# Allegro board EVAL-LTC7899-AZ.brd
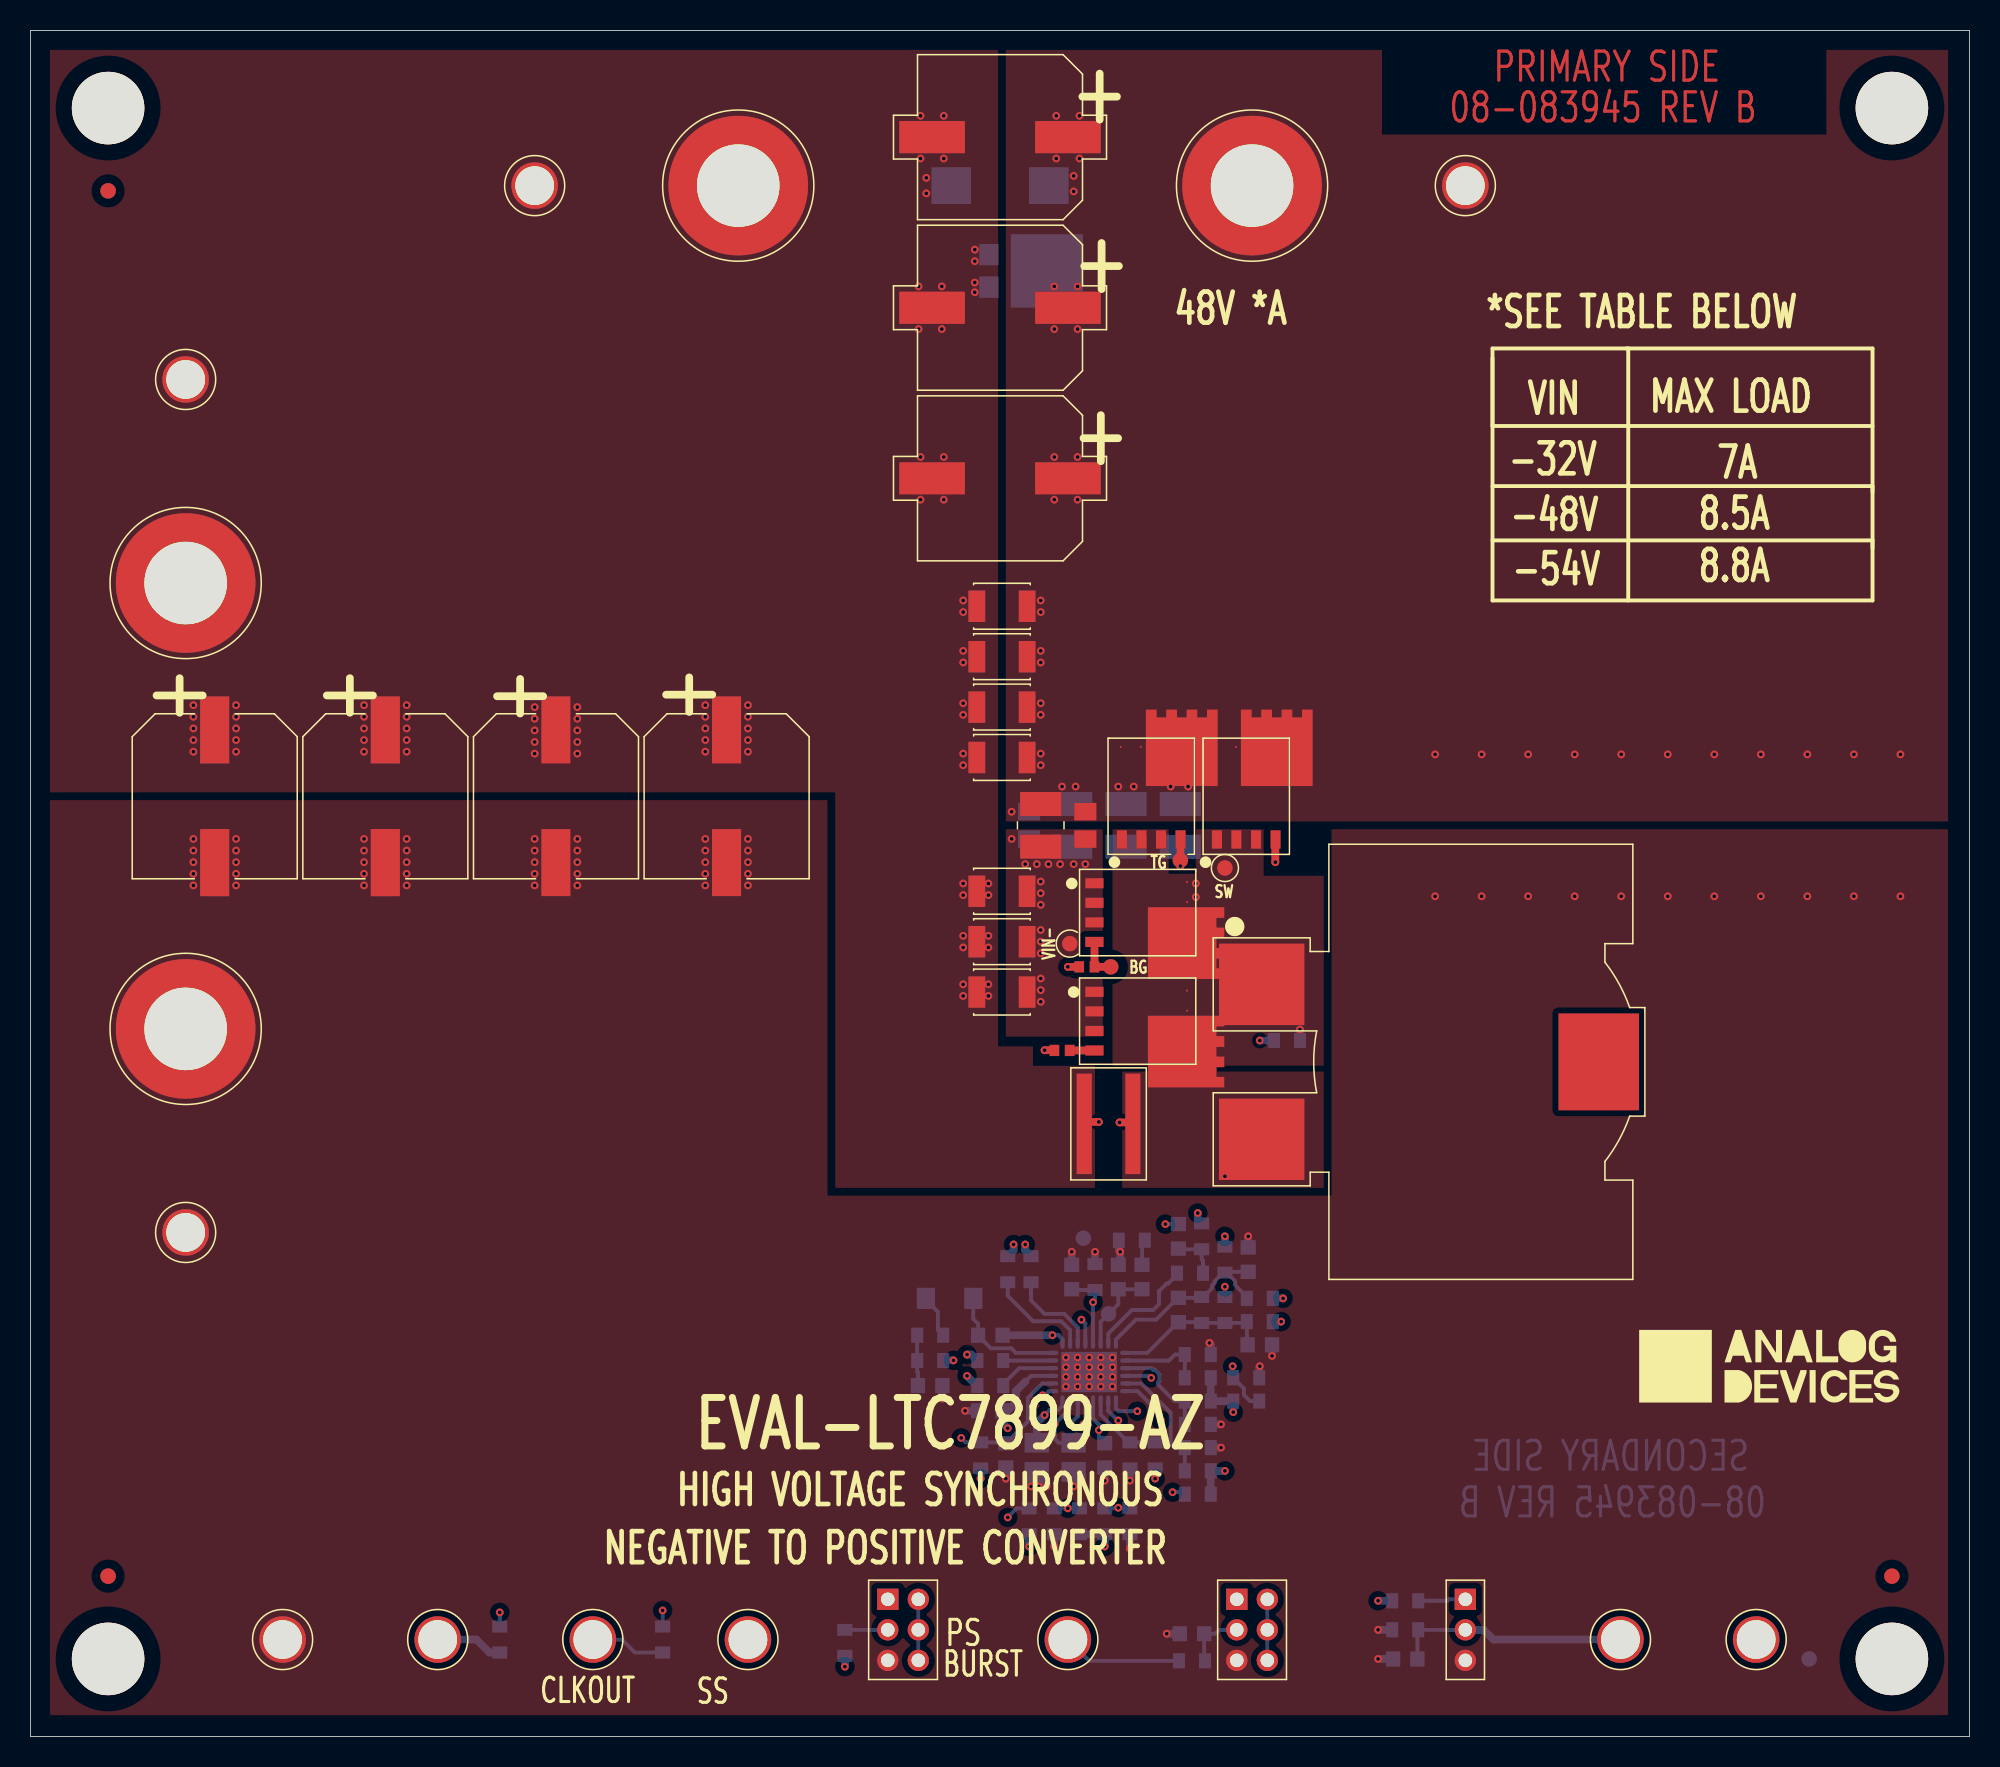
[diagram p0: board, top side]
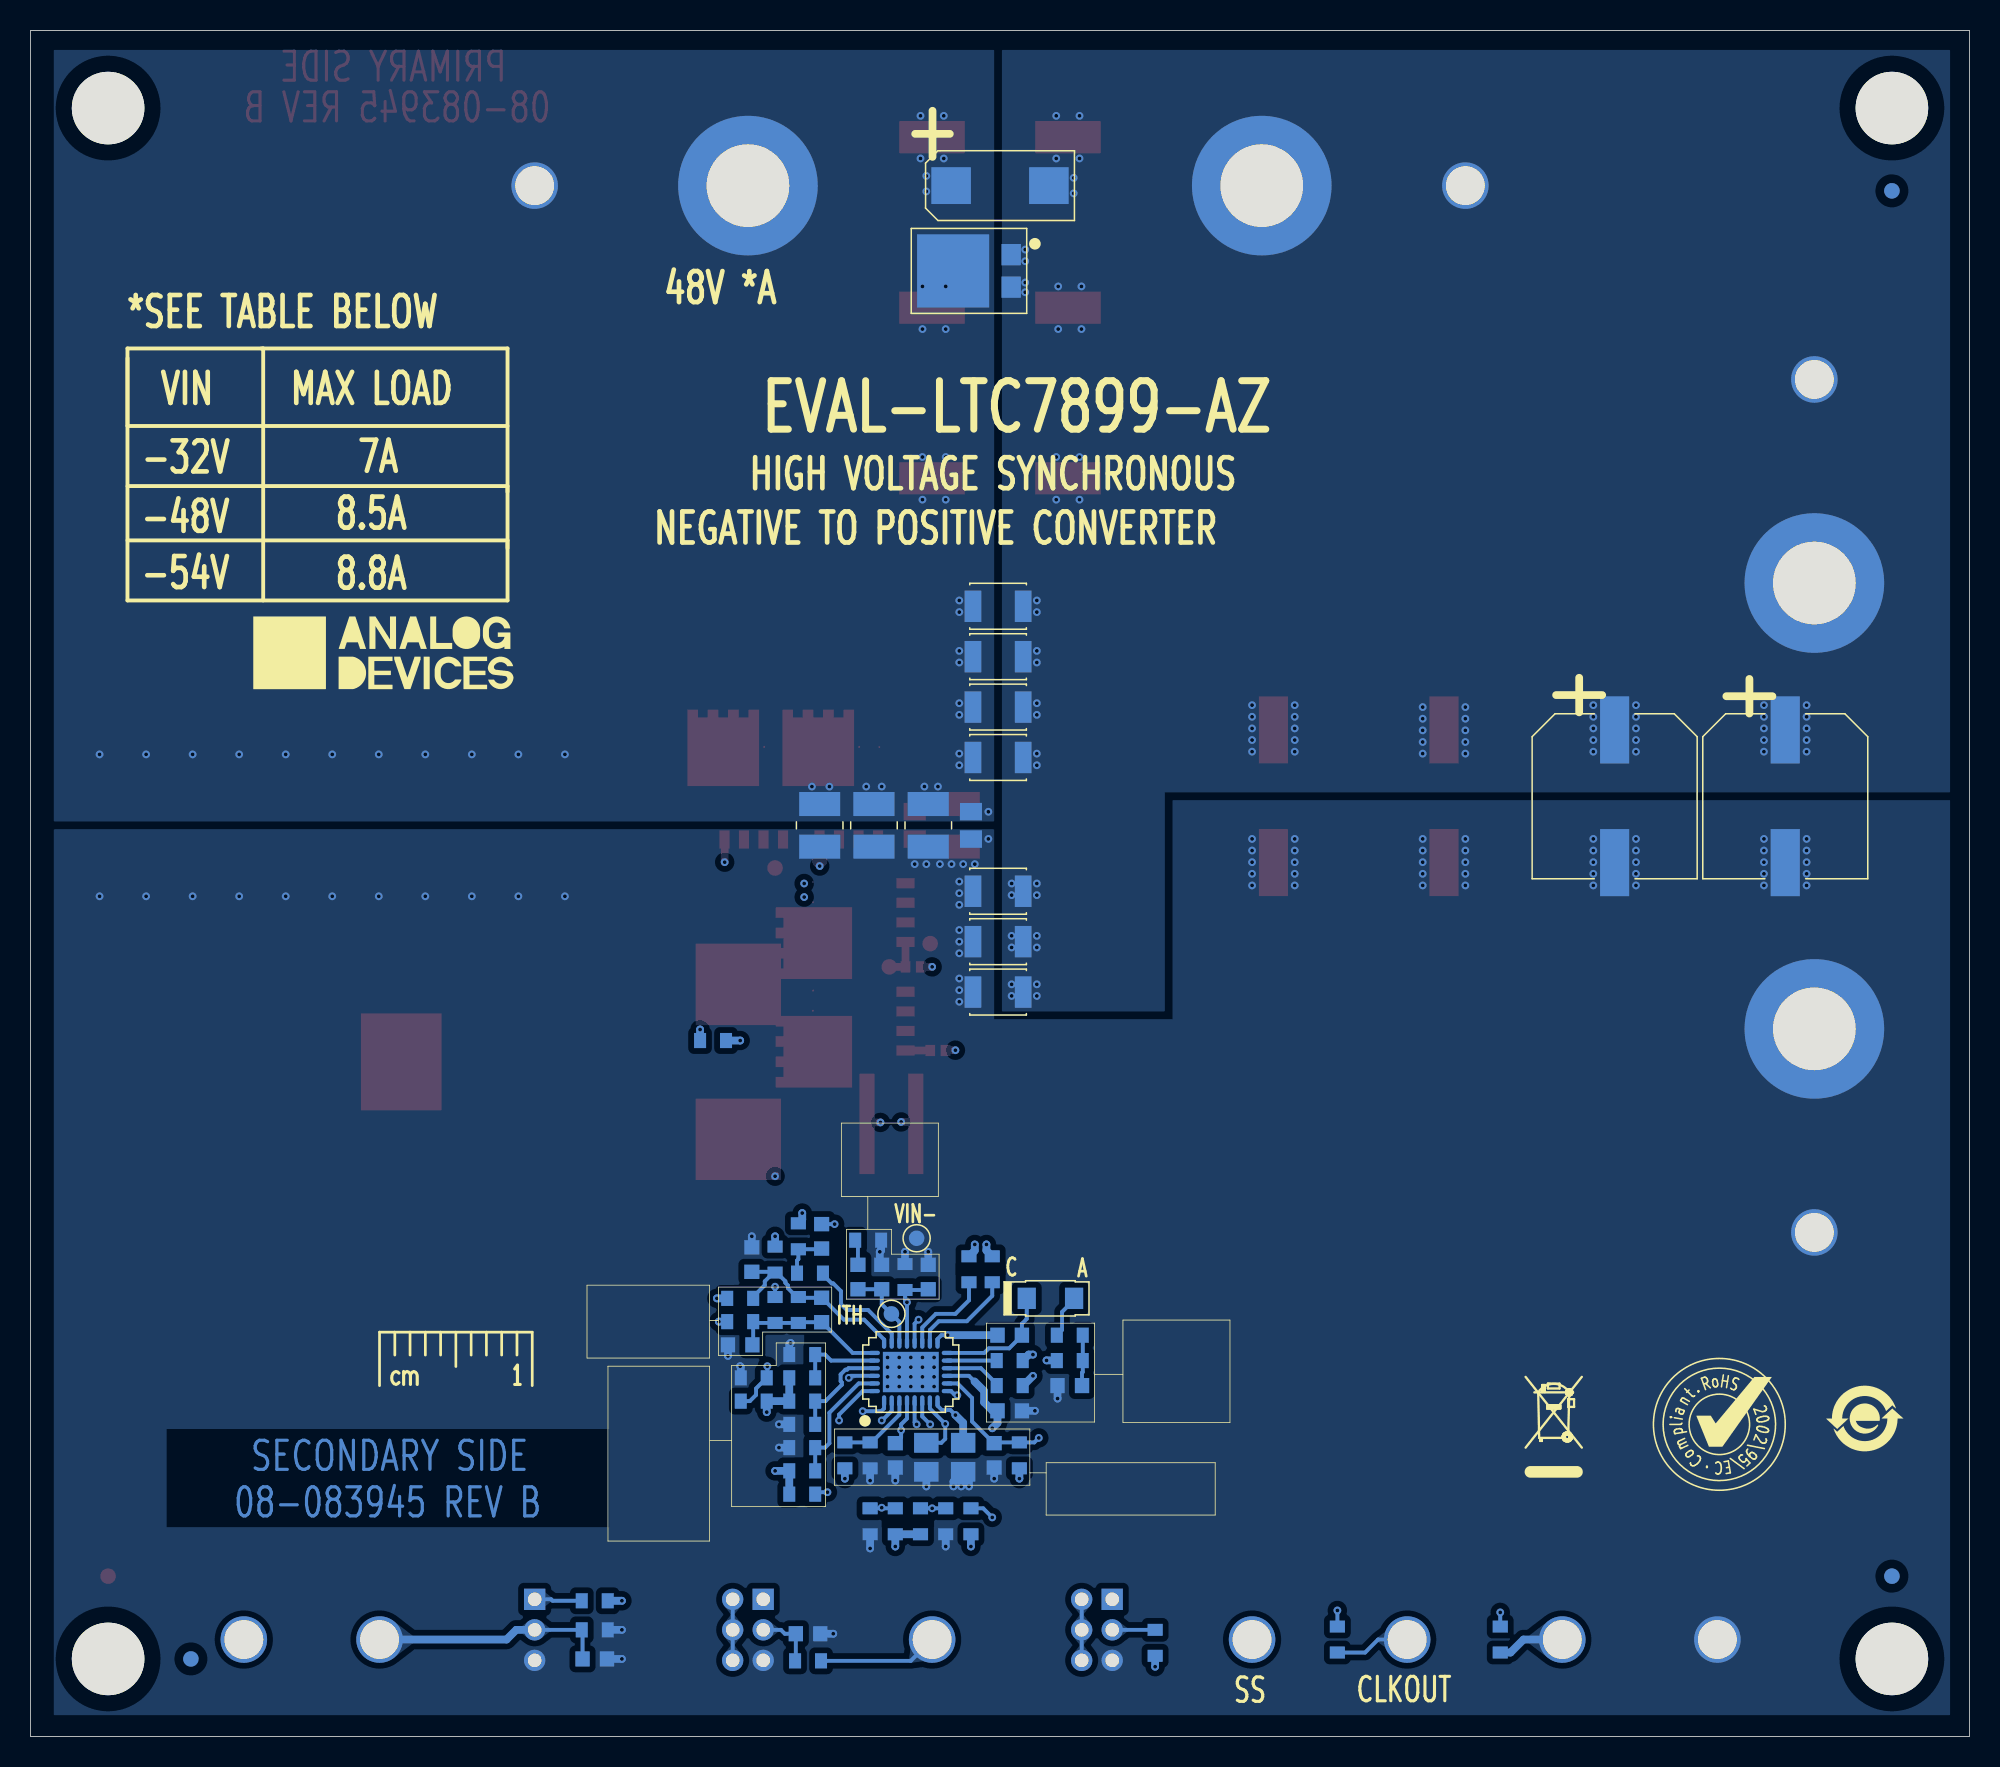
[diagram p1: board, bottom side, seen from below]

Outline 127 x 111.76 mm; copper layers: TOP, LAYER_2, LAYER_3, LAYER_4, LAYER_5, BOTTOM. Coordinates in mm from the lower left corner of the outline.
Outline path: 0,111.76 0,0 127,0 127,111.76 0,111.76

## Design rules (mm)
constraint set DEFAULT: min track width 0.254
net group _N80: nets _N80 _N81
net group _N135: nets _N40 _N135
net group _N17: nets _N17 _N18 _N19
net group _N44: nets _N42 _N43 _N44
net group _N59: nets _N52 _N53 _N54 _N59 _N60
net group _N63: nets _N45 _N46 _N63 _N64

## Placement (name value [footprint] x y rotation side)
C1  TBD0603  [C0603]  79.76 31.24 90 bottom
C2  TBD0603  [C0603]  80.52 25.65 0 bottom
C3  0.1UF  [C0603]  62.86 26.29 180 bottom
C4  56UF  [CPLSMSQ406H500]  23.24 61.59 270 bottom
C5  56UF  [CPLSMSQ406H500]  12.07 61.59 270 bottom
C6  0.22uF  [C1210-2]  66.17 59.69 270 top
C7  1000pF  [C0603]  75.18 27.94 270 bottom
C8  TBD0603  [C0603]  68.2 30.1 270 bottom
C9  0.1UF  [C0805H55]  69.09 59.69 270 top
C10  470pF  [C0603]  71.25 30.1 90 bottom
C11  0.22uF  [C1210-2]  68.2 59.69 270 bottom
C12  0.22uF  [C1210-2]  71.75 59.69 270 bottom
C13  0.22uF  [C1210-2]  75.31 59.69 270 bottom
C14  0.015UF  [C0603]  72.8 30.1 90 bottom
C15  0.1uF  [C0805H60]  68.33 18.29 270 bottom
C16  TBD0603  [C0603]  76.07 6.73 180 bottom
C17  0.1UF  [C0603]  70.36 18.41 270 bottom
C18  0.1UF  [C0805H55]  65.41 59.69 270 bottom
C19  0.1UF  [C0603]  58.93 22.99 0 bottom
C20  10UF  [C1210H106]  63.63 48.77 0 top
C21  10UF  [C1210H106]  63.63 52.07 0 top
C22  10UF  [C1210H106]  63.63 55.37 0 top
C23  TBD0603  [C0603]  63.88 18.41 270 bottom
C24  100PF  [C0603]  90.04 5.08 180 bottom
C26  0.1UF  [C0603]  62.86 21.34 180 bottom
C27  4.7uF  [C0805H53]  65.91 18.29 270 bottom
C28  TBD0603  [C0603]  75.18 32.77 90 bottom
C30  56UF  [CPLSMSQ406H500]  12.07 61.59 270 top
C31  56UF  [CPLSMSQ406H500]  23.24 61.59 270 top
C32  56UF  [CPLSMSQ406H500]  34.42 61.59 270 top
C33  56UF  [CPLSMSQ406H500]  45.59 61.59 270 top
C34  10UF  [C1210H106]  63.63 55.37 0 bottom
C35  10UF  [C1210H106]  63.63 52.07 0 bottom
C36  10UF  [C1210H106]  63.63 48.77 0 bottom
COUT1  68UF  [CPLSMSQ406H413]  63.5 104.77 180 top
COUT2  68UF  [CPLSMSQ406H413]  63.5 93.6 180 top
COUT3  68UF  [CPLSMSQ406H413]  63.5 82.42 180 top
COUT4  TBD7343  [C7343H162]  63.5 101.6 180 bottom
COUT5  10UF  [C1210H106]  63.63 74.04 180 top
COUT6  10UF  [C1210H106]  63.63 70.74 180 top
COUT7  10UF  [C1210H106]  63.63 67.44 180 top
COUT8  10UF  [C1210H106]  63.63 64.14 180 top
COUT9  10UF  [C1210H106]  63.63 74.04 180 bottom
COUT10  10UF  [C1210H106]  63.63 70.74 180 bottom
COUT11  10UF  [C1210H106]  63.63 67.44 180 bottom
COUT12  10UF  [C1210H106]  63.63 64.14 180 bottom
D1  PNE20010ERX  [SOD123W]  60.2 28.7 180 bottom
D2  SS8P3LHM3_A/H  [TO-277A]  65.53 96.01 0 bottom
E2  2501-2-00-80-00-00-07-0  [CNMILLMAX2501]  113.03 6.35 0 top
E6  2501-2-00-80-00-00-07-0  [CNMILLMAX2501]  10.16 88.9 0 top
E8  2501-2-00-80-00-00-07-0  [CNMILLMAX2501]  10.16 33.02 0 top
E10  2501-2-00-80-00-00-07-0  [CNMILLMAX2501]  67.95 6.35 0 top
E11  2501-2-00-80-00-00-07-0  [CNMILLMAX2501]  46.99 6.35 0 top
E12  2501-2-00-80-00-00-07-0  [CNMILLMAX2501]  26.67 6.35 0 top
E16  2501-2-00-80-00-00-07-0  [CNMILLMAX2501]  104.14 6.35 0 top
E18  2501-2-00-80-00-00-07-0  [CNMILLMAX2501]  33.02 101.6 0 top
E19  2501-2-00-80-00-00-07-0  [CNMILLMAX2501]  93.98 101.6 0 top
E20  2501-2-00-80-00-00-07-0  [CNMILLMAX2501]  16.51 6.35 0 top
E21  2501-2-00-80-00-00-07-0  [CNMILLMAX2501]  36.83 6.35 0 top
J1  575-4  [CNBANANAD312LD203]  80.01 101.6 0 top
J2  575-4  [CNBANANAD312LD203]  46.35 101.6 0 top
J3  575-4  [CNBANANAD312LD203]  10.16 75.56 0 top
J4  575-4  [CNBANANAD312LD203]  10.16 46.35 0 top
JP1  62000621121  [CNTHMHDR2X3L236W157H248]  56.15 8.98 270 top
JP2  62000311121  [CNTHMHDR1X3L236W79H244]  93.98 8.98 270 top
JP3  62000621121  [CNTHMHDR2X3L236W157H248]  79.01 8.98 270 top
L1  15UH  [LSML1102W764H728]  92.2 44.2 270 top
NOREF  -  []  -222.25 -135.89 0 top
NOREF#2  -  []  200.56 73.18 0 top
NOREF#3  -  []  0 111.76 0 top
NOREF#4  -  []  0 0 0 top
NOREF#5  -  []  113.92 24.26 0 top
NOREF#6  -  []  163.07 61.21 0 top
NOREF#7  -  [unnamed#2]  121.92 5.08 180 top
NOREF#8  -  []  5.08 5.08 0 top
NOREF#9  -  []  5.08 5.08 0 top
NOREF#10  -  []  152.53 -3.68 0 top
NOREF#11  -  []  -76.2 -66.04 0 top
NOREF#12  -  [unnamed#2]  5.08 106.68 180 top
NOREF#13  -  []  244.35 296.16 0 top
NOREF#14  -  []  0 0 0 top
NOREF#15  -  []  64.14 0.63 270 top
NOREF#16  -  []  163.07 54.23 0 top
NOREF#17  -  [unnamed#2]  121.92 106.68 180 top
NOREF#18  -  []  250.19 261.75 0 top
NOREF#19  -  []  0 111.76 0 top
NOREF#20  -  [unnamed#2]  5.08 10.5 0 top
NOREF#21  -  []  -76.2 -66.04 0 top
NOREF#22  -  []  152.53 -13.59 0 top
NOREF#23  -  []  127 111.76 180 top
NOREF#24  -  []  127 0 0 top
NOREF#25  -  []  127 0 90 top
NOREF#26  -  [unnamed#2]  5.08 5.08 180 top
NOREF#27  -  []  82.17 105.16 0 top
NOREF#28  -  []  59.69 117.47 0 top
NOREF#29  -  []  95 102.87 0 top
NOREF#30  -  []  0 0 0 top
NOREF#31  -  []  178.56 36.45 0 top
NOREF#32  -  []  340.83 78.68 0 top
NOREF#33  -  [unnamed#2]  5.08 101.26 180 top
NOREF#34  -  []  308.39 131.71 0 top
NOREF#35  -  []  -222.25 -135.89 0 top
NOREF#36  -  [unnamed#2]  121.92 10.5 0 top
NOREF#37  -  []  -76.2 -66.04 0 top
NOREF#38  -  []  127 0 90 top
NOREF#39  -  []  0 111.76 270 top
NOREF#40  -  []  124.08 108.46 0 top
NOREF#41  -  []  104.14 22.99 180 bottom
NOREF#42  -  [unnamed#2]  5.08 101.26 0 bottom
NOREF#43  -  []  103.86 70.99 180 bottom
NOREF#44  -  []  27.43 17.02 180 bottom
NOREF#45  -  []  16.38 20.45 180 bottom
NOREF#46  -  []  6.86 20.83 180 bottom
NOREF#47  -  [unnamed#2]  5.08 10.5 180 bottom
NOREF#48  -  [unnamed#2]  116.5 5.08 270 bottom
Q1  ISC078N12NM6ATMA1  [SON8]  73.41 61.59 0 top
Q2  ISC110N12NM6ATMA1  [SON8]  79.63 61.59 0 top
Q3  ISC078N12NM6ATMA1  [SON8]  72.52 53.98 270 top
Q4  ISC078N12NM6ATMA1  [SON8]  72.52 46.86 270 top
R1  0  [R0402]  69.19 50.42 0 top
R2  0  [R0402]  67.56 44.94 0 top
R3  0  [R0603]  72.01 14.1 90 bottom
R4  TBD0603  [R0603]  70.36 14.1 90 bottom
R5  1MEG  [R0603]  76.45 15.88 180 bottom
R6  0  [R0603]  65.53 30.61 90 bottom
R7  0  [R0603]  41.4 6.35 90 bottom
R8  0  [R0603]  64.01 30.61 90 bottom
R9  316K  [R0603]  90.04 8.89 180 bottom
R10  0  [R0603]  68.71 14.1 90 bottom
R11  TBD0603  [R0603]  67.06 14.1 90 bottom
R12  13.3K  [R0603]  90.04 6.99 180 bottom
R13  5.11  [R0603]  62.86 22.99 180 bottom
R14  TBD0603  [R0603]  76.45 18.92 0 bottom
R15  0  [R0603]  62.86 24.63 180 bottom
R16  0  [R0603]  76.45 17.4 0 bottom
R17  402K  [R0603]  75.95 30.35 180 bottom
R18  0  [R0603]  76.71 32.77 270 bottom
R19  10K  [R0603]  69.72 30.1 270 bottom
R20  10K  [R0603]  72.14 32.51 180 bottom
R21  TBD0603  [R0603]  30.73 6.35 270 bottom
R22  0  [R0603]  79.63 21.97 180 bottom
R23  TBD0603  [R0603]  79.63 23.49 0 bottom
R24  0  [R0603]  76.45 23.49 0 bottom
R25  0  [R0603]  80.52 27.18 180 bottom
R26  21K  [R0603]  76.45 25.02 0 bottom
R27  0  [R0603]  76.45 21.97 0 bottom
R28  20K  [R0603]  76.45 20.45 0 bottom
R29  51.1  [R0603]  80.52 28.7 180 bottom
R30  TBD0603  [R0603]  78.23 27.94 270 bottom
R31  0  [R0603]  58.93 26.29 180 bottom
R32  0  [R0603]  58.93 24.63 0 bottom
R33  TBD0603  [R0603]  82.3 45.59 180 bottom
R34  TBD0603  [R0603]  76.71 27.94 270 bottom
R35  TBD0603  [R0603]  78.23 31.24 270 bottom
R36  0  [R0603]  62.23 18.41 270 bottom
R37  249K  [R0603]  72.01 18.41 90 bottom
R38  TBD0603  [R0603]  73.66 18.41 90 bottom
R39  1K  [R0603]  76.07 4.95 0 bottom
R40  100K  [R0603]  53.34 6.14 90 bottom
R41  0  [R0603]  65.41 14.1 270 bottom
RSNS1  0.002  [R1225H28]  70.61 40.13 180 top
TP1  TESTPAD  [TPSMC40]  78.23 56.9 0 top
TP2  TESTPAD  [TPSMC40]  75.31 57.4 0 top
TP3  TESTPAD  [TPSMC40]  70.75 50.42 0 top
TP4  TESTPAD  [TPSMC40]  68.07 51.94 0 top
TP5  TESTPAD  [TPSMC40]  68.96 32.64 180 bottom
TP6  TESTPAD  [TPSMC40]  70.61 27.69 180 bottom
U1  LTC7899RUFD#PBF  [QFN28_5X4_PAD3_65X2_65_05-08-1712]  69.34 23.88 180 bottom

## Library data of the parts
C1 C2 C8 C16 C23 C28 = CAP: User Part Number: UPN; alternate symbols: (C0603)
C3 C7 C14 C17 C19 C24 C26 = CAP: User Part Number: UPN; Tolerance: 10; alternate symbols: (C0603); tolerance: 10
C4 C5 C30-C33 = CAPP: Tolerance: 20; User Part Number: UPN; alternate symbols: (CPLSMSQ406H500); tolerance: 20
C6 C11-C13 = CAP: Tolerance: 10; User Part Number: UPN; alternate symbols: (C1210-2); tolerance: 10
C9 C18 = CAP: User Part Number: UPN; Tolerance: 10; alternate symbols: (C0805H55); tolerance: 10
C10 = CAP: User Part Number: UPN; Tolerance: 1; alternate symbols: (C0603); tolerance: 1
C15 = CAP: Tolerance: 10; User Part Number: UPN; alternate symbols: (C0805H60); tolerance: 10
C20-C22 C34-C36 COUT5-COUT12 = CAP: Tolerance: 10; User Part Number: UPN; alternate symbols: (C1210H106); tolerance: 10
C27 = CAP: Tolerance: 10; User Part Number: UPN; alternate symbols: (C0805H53); tolerance: 10
COUT1-COUT3 = CAPP: User Part Number: UPN; Tolerance: 20; alternate symbols: (CPLSMSQ406H413); tolerance: 20
COUT4 = CAPP: User Part Number: UPN; alternate symbols: (C7343H162)
D1 = DIO: User Part Number: UPN; Tolerance: N/A; alternate symbols: (SOD123W); tolerance: N/A
D2 = DIO3P_V7: User Part Number: UPN; Tolerance: N/A; alternate symbols: (TO-277A); tolerance: N/A
E2 E6 E8 E10-E12 E16 E18-E21 = CNTP1P: User Part Number: UPN; Tolerance: N/A; alternate symbols: (CNMILLMAX2501); tolerance: N/A
J1-J4 = CNTP1P: Tolerance: N/A; User Part Number: UPN; alternate symbols: (CNBANANAD312LD203); tolerance: N/A
JP1 JP3 = CN6P_JMPRSHRT: User Part Number: UPN; Tolerance: N/A; alternate symbols: (CNTHMHDR2X3L236W157H248); tolerance: N/A
JP2 = CN3P: User Part Number: UPN; Tolerance: N/A; alternate symbols: (CNTHMHDR1X3L236W79H244); tolerance: N/A
L1 = IND: User Part Number: UPN; Tolerance: 15; alternate symbols: (LSML1102W764H728); tolerance: 15
Q1-Q4 = TRANNMOSFET8P: Tolerance: N/A; User Part Number: UPN; alternate symbols: (SON8); tolerance: N/A
R1 R2 = RES: User Part Number: UPN; Tolerance: JUMPER; alternate symbols: (R0402); tolerance: JUMPER
R3 R6-R8 R10 R15 R16 R18 R22 R24 R25 R27 R31 R32 R36 R41 = RES: User Part Number: UPN; Tolerance: JUMPER; alternate symbols: (R0603); tolerance: JUMPER
R4 R11 R14 R21 R23 R30 R33-R35 R38 = RES: User Part Number: UPN; alternate symbols: (R0603)
R5 R9 R12 R13 R17 R19 R20 R26 R28 R37 R39 R40 = RES: User Part Number: UPN; Tolerance: 1; alternate symbols: (R0603); tolerance: 1
R29 = RES: User Part Number: UPN; Tolerance: 0.5; alternate symbols: (R0603); tolerance: 0.5
RSNS1 = RES: User Part Number: UPN; Tolerance: 2; alternate symbols: (R1225H28); tolerance: 2
TP1-TP6 = NCTESTPAD: Tolerance: N/A; User Part Number: UPN; alternate symbols: (TPSMC40); tolerance: N/A
U1 = ADLTC7899: User Part Number: UPN; Tolerance: N/A; alternate symbols: (QFN28_5X4_PAD3_65X2_65_05-08-1712); tolerance: N/A

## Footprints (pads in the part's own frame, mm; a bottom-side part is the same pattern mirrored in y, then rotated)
C0603
  rect 0.94x0.991 smd: 1(-0.8,0) 2(0.8,0)
C0805H53
  rect 1.295x1.6 smd: 1(-0.953,0) 2(0.953,0)
C0805H55
  rect 1.143x1.448 smd: 1(-0.9,0) 2(0.9,0)
C0805H60
  rect 1.295x1.6 smd: 1(-0.953,0) 2(0.953,0)
C1210-2
  rect 1.575x2.692 smd: 1(-1.397,0) 2(1.397,0)
C1210H106
  rect 1.092x2.057 smd: 1(-1.646,0) 2(1.646,0)
C7343H162
  rect 2.591x2.413 smd: N(3.2,0) P(-3.2,0)
CNBANANAD312LD203
  round 9.144 hole 5.41: 1(0,0)
CNMILLMAX2501
  round 3.048 hole 2.54: 1(0,0)
CNTHMHDR1X3L236W79H244
  rect 1.397x1.397 hole 0.889: 1(0,0)
  round 1.397 hole 0.889: 2(2,0) 3(4,0)
CNTHMHDR2X3L236W157H248
  rect 1.397x1.397 hole 0.889: 1(0,0)
  round 1.397 hole 0.889: 2(0,2) 3(2,0) 4(2,2) 5(4,0) 6(4,2)
CPLSMSQ406H413
  rect 4.293x2.108 smd: N(4.45,0) P(-4.45,0)
CPLSMSQ406H500
  rect 4.394x1.905 smd: N(4.347,0) P(-4.347,0)
LSML1102W764H728
  rect 6.35x5.283 smd: (0,10.514)
  rect 5.334x5.588 smd: 1(-5.075,-11.56) 2(5.075,-11.56)
QFN28_5X4_PAD3_65X2_65_05-08-1712
  oval 0.279x0.737 smd: 1(-1.75,-1.893) 2(-1.25,-1.893) 3(-0.75,-1.893) 4(-0.25,-1.893) 5(0.25,-1.893) 6(0.75,-1.893) 7(1.25,-1.893) 8(1.75,-1.893) 15(1.75,1.893) 16(1.25,1.893) 17(0.75,1.893) 18(0.25,1.893) 19(-0.25,1.893) 20(-0.75,1.893) 21(-1.25,1.893) 22(-1.75,1.893)
  oval 0.737x0.279 smd: 9(2.393,-1.25) 10(2.393,-0.75) 11(2.393,-0.25) 12(2.393,0.25) 13(2.393,0.75) 14(2.393,1.25) 23(-2.393,1.25) 24(-2.393,0.75) 25(-2.393,0.25) 26(-2.393,-0.25) 27(-2.393,-0.75) 28(-2.393,-1.25)
  rect 3.658x2.642 smd: 29(0,0)
R0402
  rect 0.635x0.737 smd: 1(-0.5,0) 2(0.5,0)
R0603
  rect 0.787x0.991 smd: 1(-0.85,0) 2(0.85,0)
R1225H28
  rect 0.991x6.579 smd: 1(-1.595,0) 2(1.595,0)
SOD123W
  rect 1.194x1.397 smd: A(1.549,0) C(-1.549,0)
SON8
  rect 0.66x1.194 smd: 1(-1.92,-2.828) 2(-0.64,-2.828) 3(0.64,-2.828) 4(1.92,-2.828)
  custom 1.175x1.175 smd: 5(2,3.171)
  round 0.127 smd: 6(0.678,3.211) 7(-0.68,3.236) 8(-2.002,3.223)
TO-277A
  rect 1.27x1.397 smd: 1(-2.765,-1.065) 2(-2.765,1.065)
  rect 4.724x4.801 smd: 3(1.038,0)
TPSMC40
  round 1.016 smd: 1(0,0)
unnamed#2
  round 4.75 hole 4.75 unplated: (0,0)

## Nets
GND_POWER: C4.P C5.P C20.1 C21.1 C22.1 C30.P C31.P C32.P C33.P C34.1 C35.1 C36.1 COUT1.N(N2) COUT2.N(N2) COUT3.N(N2) COUT4.N(N2) COUT5.2(N2) COUT6.2(N2) COUT7.2(N2) COUT8.2(N2) COUT9.2(N2) COUT10.2(N2) COUT11.2(N2) COUT12.2(N2) D2.1 D2.2 E6.1(N1) E18.1(N1) J2.1(N1) J3.1(N1) R9.2(N2) R25.1 R41.2(N2) RSNS1.2(N2)
VIN-: C1.2(N2) C2.2(N2) C4.N(N2) C5.N(N2) C6.2(N2) C8.1 C9.2(N2) C10.2(N2) C11.2(N2) C12.2(N2) C13.2(N2) C15.2(N2) C16.2(N2) C17.2(N2) C18.2(N2) C19.2(N2) C20.2(N2) C21.2(N2) C22.2(N2) C23.2(N2) C24.2(N2) C26.2(N2) C27.2(N2) C30.N(N2) C31.N(N2) C32.N(N2) C33.N(N2) C34.2(N2) C35.2(N2) C36.2(N2) E8.1(N1) E20.1(N1) J4.1(N1) JP1.5 JP2.3(N3) JP3.5 Q3.1 Q3.2 Q3.3(S3) Q4.1 Q4.2 Q4.3(S3) R3.1 R11.1 R12.2(N2) R14.2(N2) R19.1 R20.2(N2) R23.2(N2) R26.2(N2) R28.2(N2) R37.1 TP4.1(N1) TP5.1(N1) U1.29(VIN-)
_N2: JP3.2 JP3.4 JP3.6(S6) U1.1
_N5: C16.1 JP3.3 R39.2(N2)
_N13: JP1.2 JP1.4 JP1.6(S6) U1.2
_N16: JP1.3 R40.2(N2)
_N17: C28.1 R17.1 R18.2(N2)
_N18: R17.2(N2) U1.21
_N19: C8.2(N2) C28.2(N2) R19.2(N2) U1.19
_N21: E10.1(N1) R39.1
_N24: R37.2(N2) R38.2(N2) U1.3
_N25: C17.1 E11.1(N1) U1.4
_N26: JP2.1 R9.1
_N27: C24.1 E16.1(N1) JP2.2 R12.1 U1.28
_N29: R3.2(N2) R4.2(N2) U1.5
_N30: R7.2(N2) U1.9
_N31: E21.1(N1) R7.1
_N32: E2.1(N1) R5.2(N2) U1.18
_N35: R10.2(N2) R11.2(N2) U1.6
_N39: R14.1 R16.1 U1.27
_N40: C23.1 R21.1 R36.1 U1.10
_N42: R6.1 U1.17
_N43: R8.1 U1.16
_N44: Q1.4 Q2.4 R6.2(N2) R8.2(N2) TP2.1(N1)
_N45: C3.1 L1.1 Q1.1 Q1.2 Q1.3(S3) Q2.1 Q2.2 Q2.3(S3) Q3.5 Q3.6 Q3.7 Q3.8 Q4.5 Q4.6 Q4.7 Q4.8 R33.1 TP1.1(N1) U1.15
_N46: C3.2(N2) D1.C U1.14
_N52: R13.1 U1.12
_N53: R15.1 U1.13
_N54: R1.1 R2.1 R13.2(N2) R15.2(N2)
_N59: Q3.4 R1.2(N2) TP3.1(N1)
_N60: Q4.4 R2.2(N2)
_N61: D1.A(P) R31.1
_N62: C19.1 R31.2(N2) R32.1
_N63: L1.2(N2) R29.1 R30.1 RSNS1.1
_N64: R33.2(N2) R35.1
_N70: R22.1 R23.1 U1.26
_N74: R24.1 R26.1 U1.24
_N78: R27.1 R28.1 U1.25
_N80: C14.2(N2) R20.1
_N81: C10.1 C14.1 TP6.1(N1) U1.20
_N132: C15.1 R41.1 U1.7
_N135: E12.1(N1) R21.2(N2)
DRVCC: C27.1 R32.2(N2) U1.8
INTVCC: C26.1 JP1.1 JP3.1 R4.1 R5.1 R10.1 R16.2(N2) R22.2(N2) R24.2(N2) R27.2(N2) R36.2(N2) R38.1 R40.1 U1.11
SENSE+: C2.1 C7.2(N2) R25.2(N2) R30.2(N2) R34.2(N2) U1.23
SENSE-: C1.1 C7.1 R29.2(N2) R34.1 R35.2(N2) U1.22
VOUT: C6.1 C9.1 C11.1 C12.1 C13.1 C18.1 COUT1.P COUT2.P COUT3.P COUT4.P COUT5.1 COUT6.1 COUT7.1 COUT8.1 COUT9.1 COUT10.1 COUT11.1 COUT12.1 D2.3(C) E19.1(N1) J1.1(N1) Q1.5 Q1.6 Q1.7 Q1.8 Q2.5 Q2.6 Q2.7 Q2.8 R18.1

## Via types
v1: diameter 0.508, hole 0.254, TOP to BOTTOM, 280 vias

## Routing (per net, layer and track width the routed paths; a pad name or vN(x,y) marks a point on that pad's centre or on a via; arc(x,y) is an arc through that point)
GND_POWER: length 25
  TOP w0.508: RSNS1.2 69.14,40.26 v1(69.98,40.26)
  LAYER_5 w0.508: v1(69.98,40.26) 70.72,39.52 76.99,39.52 81.33,35.18 81.33,27.76 v1(81.91,27.18)
  BOTTOM w0.508: R41.2 v1(65.41,12.45) ; R9.2 v1(88.27,8.89) ; R25.1 v1(81.91,27.18)
  vias: v1(10.67,67.56) v1(10.67,66.8) v1(10.67,66.04) v1(10.67,65.28) v1(10.67,64.52) v1(13.46,67.56) v1(13.46,66.8) v1(13.46,66.04) v1(13.46,65.28) v1(13.46,64.52) v1(21.84,67.56) v1(21.84,66.8) v1(21.84,66.04) v1(21.84,65.28) v1(21.84,64.52) v1(24.64,67.56) v1(24.64,66.8) v1(24.64,66.04) v1(24.64,65.28) v1(24.64,64.52) v1(33.02,67.44) v1(33.02,66.67) v1(33.02,65.91) v1(33.02,65.15) v1(33.02,64.39) v1(35.81,67.44) v1(35.81,66.67) v1(35.81,65.91) v1(35.81,65.15) v1(35.81,64.39) v1(44.2,67.56) v1(44.2,66.8) v1(44.2,66.04) v1(44.2,65.28) v1(44.2,64.52) v1(46.99,67.56) v1(46.99,66.8) v1(46.99,66.04) v1(46.99,65.28) v1(46.99,64.52) v1(58.17,95) v1(58.17,92.2) v1(58.29,106.17) v1(58.29,103.38) v1(58.29,83.82) v1(58.29,81.03) v1(58.67,102.11) v1(58.67,101.09) v1(59.69,95) v1(59.69,92.2) v1(59.82,106.17) v1(59.82,103.38) v1(59.82,83.82) v1(59.82,81.03) v1(61.09,74.42) v1(61.09,73.66) v1(61.09,71.12) v1(61.09,70.36) v1(61.09,67.69) v1(61.09,66.93) v1(61.09,64.39) v1(61.09,63.63) v1(61.09,55.88) v1(61.09,55.12) v1(61.09,52.45) v1(61.09,51.69) v1(61.09,49.28) v1(61.09,48.51) v1(61.85,97.41) v1(61.85,96.65) v1(61.85,95.25) v1(61.85,94.61) v1(62.74,55.88) v1(62.74,55.12) v1(62.74,52.45) v1(62.74,51.69) v1(62.74,49.28) v1(62.74,48.51)
VIN-: length 20.5
  BOTTOM w0.508: C26.2 v1(61.21,21.34) ; v1(77.22,25.78) 77.3,25.69 R26.2 ; C16.2 v1(74.42,6.73) ; R28.2 v1(77.98,20.45) ; C17.2 v1(70.36,16.76) ; C23.2 v1(63.88,16.89) ; R11.1 v1(67.06,12.45) ; R23.2 80.48,24.22 v1(80.52,24.26) ; 71.37,30.9 v1(71.37,31.75) 71.29,31.84 R20.2 ; C27.2 65.53,16.95 v1(65.53,16.38) ; C27.2 66.55,16.7 v1(66.55,16.38) ; C27.2 65.91,16.74 66.04,16.61 v1(66.04,16.38) ; C8.1 v1(68.2,31.75) ; C15.2 v1(68.33,16.38) ; R14.2 v1(77.98,18.92) ; R37.1 v1(72.01,16.76) ; C19.2 v1(59.73,22.14) ; C24.2 v1(88.27,5.08) ; C1.2 v1(79.76,32.77) ; R3.1 v1(72.01,12.32) ; R19.1 v1(69.72,31.75) ; C2.2 v1(81.32,24.93) ; R12.2 v1(88.27,6.99)
  vias: v1(10.67,58.8) v1(10.67,58.04) v1(10.67,57.28) v1(10.67,56.52) v1(10.67,55.75) v1(13.46,58.8) v1(13.46,58.04) v1(13.46,57.28) v1(13.46,56.52) v1(13.46,55.75) v1(21.84,58.8) v1(21.84,58.04) v1(21.84,57.28) v1(21.84,56.52) v1(21.84,55.75) v1(24.64,58.8) v1(24.64,58.04) v1(24.64,57.28) v1(24.64,56.52) v1(24.64,55.75) v1(33.02,58.8) v1(33.02,58.04) v1(33.02,57.28) v1(33.02,56.52) v1(33.02,55.75) v1(35.81,58.8) v1(35.81,58.04) v1(35.81,57.28) v1(35.81,56.52) v1(35.81,55.75) v1(44.2,58.8) v1(44.2,58.04) v1(44.2,57.28) v1(44.2,56.52) v1(44.2,55.75) v1(46.99,58.8) v1(46.99,58.04) v1(46.99,57.28) v1(46.99,56.52) v1(46.99,55.75) v1(64.26,58.8) v1(65.15,57.15) v1(65.91,57.15) v1(66.17,56.01) v1(66.17,55.24) v1(66.17,54.48) v1(66.17,52.83) v1(66.17,52.07) v1(66.17,51.31) v1(66.17,49.66) v1(66.17,48.89) v1(66.17,48.13) v1(66.67,57.15) v1(67.44,57.15) v1(67.82,24.83) v1(67.82,24.19) v1(67.82,23.56) v1(67.82,22.92) v1(68.33,57.15) v1(68.58,24.83) v1(68.58,24.19) v1(68.58,23.56) v1(68.58,22.92) v1(69.09,57.15) v1(69.34,24.83) v1(69.34,24.19) v1(69.34,23.56) v1(69.34,22.92) v1(70.1,24.83) v1(70.1,24.19) v1(70.1,23.56) v1(70.1,22.92) v1(70.87,24.83) v1(70.87,24.19) v1(70.87,23.56) v1(70.87,22.92) v1(92,55.04) v1(95.05,55.04) v1(98.09,55.04) v1(101.14,55.04) v1(104.19,55.04) v1(107.24,55.04) v1(110.29,55.04) v1(113.33,55.04) v1(116.38,55.04) v1(119.43,55.04) v1(122.48,55.04)
_N2: length 23.6
  LAYER_4 w0.254: JP3.2 78.56,11.43 75.56,11.43 72.77,14.22 72.77,18.54 72.49,18.82 v1(72.49,21.31)
  BOTTOM w0.254: JP3.2 JP3.6 ; U1.1 71.09,21.49 71.27,21.31 v1(72.49,21.31)
_N5: length 4
  BOTTOM w0.254: R39.2 76.87,5 C16.1 77.6,6.73 77.85,6.99 JP3.3
_N13: length 27.2
  LAYER_4 w0.254: JP1.2 60.21,11.05 67.95,11.05 69.34,12.45 69.34,16.97 71.25,18.87 v1(71.25,20.7)
  BOTTOM w0.254: U1.2 70.59,21.33 71.22,20.7 v1(71.25,20.7) ; JP1.6 JP1.2
_N16: length 2.8
  BOTTOM w0.254: R40.2 JP1.3
_N17: length 3.1
  BOTTOM w0.254: R17.1 76.8,31.18 76.71,31.27 R18.2 75.23,31.92 C28.1
_N18: length 7.3
  BOTTOM w0.254: U1.21 70.59,26.39 72.14,27.94 73.53,27.94 73.91,28.32 73.91,29.17 74.42,29.68 74.52,29.68 75.1,30.25 R17.2
_N19: length 14.5
  LAYER_3 w0.254: v1(74.33,33.57) 74.33,31.03 71.75,28.45 v1(69.6,28.45)
  BOTTOM w0.254: 69.72,28.6 69.72,28.58 v1(69.6,28.45) ; 69.72,28.6 R19.2 68.25,29.25 C8.2 ; 69.72,28.6 69.59,28.47 U1.19 ; C28.2 v1(74.33,33.57)
_N21: length 7.9
  BOTTOM w0.254: E10.1 69.34,4.95 R39.1
_N24: length 5.2
  BOTTOM w0.254: U1.3 70.09,21.08 71.91,19.26 R37.2 R38.2
_N25: length 31.8
  LAYER_4 w0.254: E11.1 56.26,15.62 63.88,15.62 66.17,17.91 67.82,17.91 v1(69.98,20.07)
  BOTTOM w0.254: U1.4 69.59,20.83 69.98,20.44 v1(69.98,20.07) 69.98,19.6 C17.1
_N26: length 3.1
  BOTTOM w0.254: JP2.1 92.9,8.98 92.81,8.89 R9.1
_N27: length 45.3
  LAYER_4 w0.254: v1(74.04,20.7) 74.04,19.05 81.53,11.56 89.41,11.56 JP2.2
  BOTTOM w0.254: v1(74.04,20.7) 74.04,21.08 72.5,22.63 U1.28 ; C24.1 90.84,6.94 R12.1 JP2.2
  BOTTOM w0.508: JP2.2 95.19,6.99 95.82,6.35 E16.1
_N29: length 9.7
  LAYER_3 w0.254: v1(71.25,14.99) 68.96,17.27 v1(68.96,20.45)
  BOTTOM w0.254: R4.2 71.21,14.95 ; 71.21,14.95 v1(71.25,14.99) ; 71.21,14.95 R3.2 ; v1(68.96,20.45) 69.09,20.58 U1.5
_N30: length 32.6
  LAYER_3 w0.254: v1(41.4,8.25) 50.55,17.4 59.69,17.4 64.64,22.35 v1(66.29,22.35)
  BOTTOM w0.254: v1(66.29,22.35) 66.37,22.43 66.51,22.43 66.71,22.63 U1.9 ; v1(41.4,8.25) R7.2
_N31: length 4.9
  BOTTOM w0.254: E21.1 38.73,6.35 39.58,5.5 R7.1
_N32: length 62.7
  LAYER_3 w0.254: v1(74.8,16) 74.8,24.77 72.26,27.3 v1(68.83,27.3)
  LAYER_4 w0.254: v1(74.8,16) 75.69,16 88.01,3.68 110.36,3.68 E2.1
  BOTTOM w0.254: v1(68.83,27.3) 69.09,27.05 U1.18 ; v1(74.8,16) 75.48,16 R5.2
_N35: length 9.4
  LAYER_3 w0.254: v1(68.07,20.45) 67.44,19.81 67.44,15.45 v1(67.95,14.95)
  BOTTOM w0.254: R11.2 v1(67.95,14.95) R10.2 ; U1.6 68.59,20.97 v1(68.07,20.45)
_N39: length 8.3
  BOTTOM w0.254: R16.1 R14.1 74.96,18.92 74.68,19.2 74.68,21.21 72.76,23.13 U1.27
_N40: length 44.5
  LAYER_3 w0.254: v1(60.96,19.56) 59.56,18.16 40.77,18.16 v1(30.73,8.13)
  BOTTOM w0.254: v1(60.96,19.56) 61.25,19.26 R36.1 63.83,19.26 C23.1 63.91,19.22 65.33,20.64 65.33,22.17 66.28,23.13 U1.10 ; v1(30.73,8.13) R21.1
_N42: length 6
  BOTTOM w0.254: U1.17 68.59,26.79 67.7,27.69 66.42,27.69 65.53,28.58 R6.1
_N43: length 6.8
  BOTTOM w0.254: U1.16 68.09,26.62 67.51,27.2 65.67,27.2 64.01,28.87 R8.1
_N44: length 70
  TOP w0.508: v1(81.53,57.28) 81.53,58.75 Q2.4 ; Q1.4 75.31,58.75 TP2.1 v1(75.31,57.02)
  LAYER_3 w0.508: v1(81.53,57.28) 81.28,57.02 v1(75.31,57.02) ; v1(75.31,57.02) 75.31,50.29 65.15,40.13 v1(65.15,32.23) ; v1(75.31,57.02) 74.88,57.02 74.37,56.52 74.37,50.75 64.39,40.77 v1(64.39,32.23)
  BOTTOM w0.508: v1(65.15,32.23) 65.15,31.84 R6.2 ; v1(64.39,32.23) 64.39,31.84 R8.2
_N45: length 5
  BOTTOM w0.254: v1(66.93,26.29) 67.34,26.29 67.59,26.03 U1.15
  BOTTOM w0.508: v1(66.93,26.29) C3.1 ; R33.1 v1(83.15,46.32)
  vias: v1(76.33,55.88) v1(76.33,54.99)
_N46: length 7.9
  BOTTOM w0.254: U1.14 64.54,25.13 64.24,25.43 62.9,25.43 62.06,26.26 C3.2 62.06,27.04 61.75,27.36 D1.C
_N52: length 3.8
  BOTTOM w0.254: R13.1 63.71,23.09 64.75,24.13 U1.12
_N53: length 3.2
  BOTTOM w0.254: U1.13 R15.1
_N54: length 55.1
  TOP w0.508: v1(66.42,44.96) 67.05,44.96 R2.1 ; v1(67.95,50.42) R1.1
  LAYER_4 w0.508: v1(67.95,50.42) 67.95,47.24 66.42,45.72 v1(66.42,44.96) ; v1(61.34,23.62) 62.23,24.51 62.23,39.8 66.42,43.99 v1(66.42,44.96) ; v1(61.34,25.02) 61.34,40.44 65.86,44.96 v1(66.42,44.96)
  BOTTOM w0.508: R15.2 61.62,25.02 v1(61.34,25.02) ; R13.2 61.98,22.99 v1(61.34,23.62)
_N59: length 2.7
  TOP w0.508: Q3.4 R1.2 TP3.1
_N60: length 1.6
  TOP w0.508: R2.2 Q4.4
_N61: length 2.9
  BOTTOM w0.254: R31.1 59.44,26.63 59.44,27.81 58.65,28.6 D1.A
_N62: length 3.3
  BOTTOM w0.254: C19.1 58.13,23.83 58.08,23.88 R32.1 R31.2
_N63: length 29.7
  TOP w0.508: v1(71.33,40.23) 72.11,40.23 RSNS1.1
  LAYER_4 w0.508: v1(78.23,36.7) 77.34,35.81 77.34,30.35 v1(78.23,29.46)
  LAYER_5 w0.508: v1(82.04,28.7) 82.04,35.56 77.37,40.23 v1(71.33,40.23)
  BOTTOM w0.254: R30.1 v1(78.23,29.46)
  BOTTOM w0.508: R29.1 v1(82.04,28.7)
_N64: length 15.4
  LAYER_3 w0.508: v1(80.52,45.59) 78.99,44.07 78.99,35.94 78.23,35.18 v1(78.23,32.77)
  BOTTOM w0.508: R35.1 v1(78.23,32.77) ; v1(80.52,45.59) R33.2
_N70: length 10.7
  LAYER_4 w0.254: v1(73.41,23.49) 77.98,23.49 v1(78.74,24.26)
  BOTTOM w0.254: U1.26 73.27,23.63 v1(73.41,23.49) ; R22.1 79.88,21.97 79.48,22.38 79.48,22.8 R23.1 78.74,23.53 v1(78.74,24.26)
_N74: length 5.6
  BOTTOM w0.254: U1.24 74.56,24.63 74.96,25.02 R26.1 R24.1
_N78: length 6.8
  BOTTOM w0.254: U1.25 73.42,24.13 73.52,24.03 73.63,24.03 73.94,23.72 73.94,23.27 73.86,23.2 73.86,23.04 74.93,21.97 R27.1 R28.1
_N80: length 1.7
  BOTTOM w0.254: R20.1 72.8,32.33 C14.2
_N81: length 5.6
  BOTTOM w0.254: U1.20 70.09,27.17 TP6.1 71.25,28.32 C10.1 C14.1
_N132: length 13.3
  LAYER_3 w0.254: v1(64.01,14.35) 64.77,15.11 64.77,18.16 v1(67.09,20.48)
  BOTTOM w0.254: C15.1 67.34,19.24 67.09,19.49 v1(67.09,20.48) 68.09,21.48 U1.7 ; v1(64.01,14.35) 64.6,14.95 R41.1
_N135: length 4.4
  BOTTOM w0.508: R21.2 30.06,5.5 29.21,6.35 E12.1
DRVCC: length 12.6
  LAYER_4 w0.508: v1(66.42,21.06) 62.76,21.06 60.45,23.37 v1(60.45,24.64)
  BOTTOM w0.254: v1(66.42,21.06) 66.75,21.39 67.31,21.39 67.59,21.67 U1.8
  BOTTOM w0.508: R32.2 59.79,24.64 v1(60.45,24.64) ; v1(66.42,21.06) 65.91,20.55 C27.1
INTVCC: length 86.6
  LAYER_3 w0.508: 73.66,13.08 v1(73.66,16.89) ; 73.66,13.08 76.58,13.08 ; 73.66,13.08 70.99,13.08 v1(70.36,12.45) ; 76.58,13.08 78.23,14.73 v1(78.23,17.4) 78.78,17.95 v1(78.78,21.25) ; 76.58,13.08 79.01,10.65 JP3.1 ; JP1.1 54.07,8.98 53.34,8.25 v1(53.34,4.57) 53.34,3.81 54.23,2.92 59.69,2.92 66.57,9.8 69.44,9.8 70.36,10.72 v1(70.36,12.45) ; v1(70.36,12.45) 69.47,12.45 68.58,13.34 63.12,13.34 62.23,14.22 v1(62.23,16.89) 62.23,18.41 v1(64.01,20.19)
  BOTTOM w0.254: 65.16,23.25 65.54,23.63 U1.11
  BOTTOM w0.508: R24.2 R27.2 R22.2 v1(78.78,21.25) ; R5.1 R16.2 v1(78.23,17.4) ; 65.16,23.25 64.54,22.63 64.54,21.89 63.98,21.34 C26.1 63.67,20.54 v1(64.01,20.19) ; R38.1 v1(73.66,16.89) ; R36.2 v1(62.23,16.89) ; R10.1 R4.1 v1(70.36,12.45) ; R40.1 v1(53.34,4.57)
SENSE+: length 10.4
  BOTTOM w0.254: C2.1 79.67,25.7 R25.2 79.58,27.09 R30.2 R34.2 76.66,27.14 C7.2 75.16,27.14 73.14,25.13 U1.23
SENSE-: length 13.2
  BOTTOM w0.254: R29.2 79.67,28.8 78.91,29.56 78.91,29.82 78.33,30.39 R35.2 ; R35.2 78.28,30.44 C1.1 ; R35.2 78.13,30.39 77.56,29.82 77.56,29.72 77.38,29.54 77.38,29.36 76.81,28.79 R34.1 76.66,28.74 C7.1 75.16,28.74 73.72,27.3 72.4,27.3 71.09,26 U1.22
VOUT: length 70.5
  LAYER_3 w0.508: v1(76.45,34.29) 76.45,32.77 77.47,31.75 83.57,31.75 85.98,34.16 85.98,70.23 82.55,73.66 v1(66.17,73.66)
  BOTTOM w0.508: R18.1 76.45,33.87 v1(76.45,34.29)
  vias: v1(64.26,60.58) v1(66.17,74.42) v1(66.17,71.12) v1(66.17,70.36) v1(66.17,67.69) v1(66.17,66.93) v1(66.17,64.39) v1(66.17,63.63) v1(67.06,95) v1(67.06,92.2) v1(67.06,83.82) v1(67.06,81.03) v1(67.18,106.17) v1(67.18,103.38) v1(67.56,62.23) v1(68.33,102.23) v1(68.33,101.22) v1(68.45,62.23) v1(68.58,95) v1(68.58,92.2) v1(68.58,83.82) v1(68.58,81.03) v1(68.71,106.17) v1(68.71,103.38) v1(71.25,62.23) v1(72.26,62.23) v1(74.68,62.23) v1(75.82,62.23) v1(92,64.34) v1(95.05,64.34) v1(98.09,64.34) v1(101.14,64.34) v1(104.19,64.34) v1(107.24,64.34) v1(110.29,64.34) v1(113.33,64.34) v1(116.38,64.34) v1(119.43,64.34) v1(122.48,64.34)

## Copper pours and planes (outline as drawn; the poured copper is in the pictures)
GND_POWER on TOP: 1.27,110.49 63.37,110.49 63.37,45.21 65.66,45.21 65.66,43.94 69.72,43.94 69.72,40.77 69.41,40.26 69.72,39.75 69.72,35.94 52.7,35.94 52.7,61.85 1.27,61.85
GND_POWER on BOTTOM: 1.27,61.85 52.7,61.85 52.7,47.5 63.37,47.5 63.37,110.49 1.27,110.49
GND_POWER on LAYER_3: 1.27,110.49 1.27,1.4 125.6,1.4 125.6,110.49 ; 2 cut-outs
GND_POWER on LAYER_4: 1.27,12.19 1.27,110.49 125.73,110.49 125.73,12.19 ; 2 cut-outs
VIN- on TOP: 70.23,45.85 63.88,45.85 63.88,59.44 70.23,59.44 70.23,52.58 68.71,52.58 68.71,51.05 67.95,51.05 67.95,49.78 70.23,49.78
VIN- on TOP: 1.27,61.34 52.2,61.34 52.2,35.43 85.22,35.43 85.22,59.44 125.6,59.44 125.6,1.4 1.27,1.4
VIN- on BOTTOM: 1.27,61.34 52.2,61.34 52.2,46.99 63.88,46.99 63.88,59.44 125.48,59.44 125.48,1.4 1.27,1.4 ; 14 cut-outs
VIN- on LAYER_2: 1.4,110.49 1.4,1.27 125.73,1.27 125.73,110.49
VIN- on LAYER_4: 1.27,11.18 1.27,1.14 125.73,1.14 125.73,11.18
VIN- on LAYER_5: 1.27,110.36 1.27,1.4 125.6,1.4 125.6,110.36
_N45 on TOP: 76.33,59.44 80.77,59.44 80.77,56.39 84.71,56.39 84.71,43.94 70.87,43.94 70.87,49.29 71.59,49.66 71.88,50.42 71.59,51.18 70.87,51.54 70.87,59.44 74.55,59.44 74.55,56.52 76.33,56.52
_N45 on LAYER_4: 82.87,58.17 75.12,58.17 73.72,56.77 73.72,50.41 63.65,40.34 63.65,31.53 63.94,31.24 65.6,31.24 66.1,30.73 66.1,25.91 66.36,25.65 67.37,25.65 67.88,26.16 67.88,41.27 77.28,50.67 77.28,56.01 77.66,56.39 82.87,56.39 82.99,56.52 82.99,58.04
_N63 on TOP: 71.5,43.56 84.71,43.56 84.71,35.94 71.5,35.94 71.5,39.71 71.82,39.91 71.94,40.26 71.82,40.61 71.5,40.81
VOUT on TOP: 117.63,110.49 125.6,110.49 125.6,59.94 63.88,59.94 63.88,110.49 88.52,110.49 88.52,104.95 117.63,104.95
VOUT on BOTTOM: 63.88,110.49 63.88,59.94 125.48,59.94 125.48,110.49

Small or netless copper shapes (teardrops, artwork), in the pictures only: 43 on BOTTOM, 18 on LAYER_3, 12 on LAYER_4

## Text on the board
Ref Des/Silkscreen Bottom: A | C | VIN- | ITH | HIGH VOLTAGE SYNCHRONOUS | NEGATIVE TO POSITIVE CONVERTER | 7A | 8.5A | 8.8A | MAX LOAD | VIN | -32V | -48V | -54V | *SEE TABLE BELOW | EVAL-LTC7899-AZ | +
User.Comments: SEE BANANA JACK DETAIL AT 4 PLACES | SEE TURRETS DETAIL AT 11 PLACES | SEE STANDOFFS DETAIL AT 4 PLACES | TURRETS (MFG_PN: 2501-2-00-80-00-00-07-0) | JP3 SHUNT : FIX FREQ (PIN 5 & PIN 6) | JP2 SHUNT : ON (PIN 1 & PIN 2) | JP1 SHUNT : FCM (PIN 1 & PIN 2) | (MFG_PN: 8831) | 5.    INSTALL SHUNT (MFG_PN: 60800213421) TO THE FOLLOWING | 4.    RoHS COMPLIANCE: ASSEMBLY VENDOR SHOULD ASSURE COMPLIANCE | WITH LEAD-FREE AND RoHS PCB ASSEMBLY STANDARDS (EU RoHS | JUMPER CONNECTOR: | DIRECTIVE 2002/95/EC).
Ref Des/Silkscreen Top: BG | TG | SW | VIN- | NEGATIVE TO POSITIVE CONVERTER | HIGH VOLTAGE SYNCHRONOUS | *SEE TABLE BELOW | -32V | -48V | -54V | VIN | MAX LOAD | 8.5A | 8.8A | 7A | EVAL-LTC7899-AZ
PAGE_OUTLINE: B | CHANGES AS PER ECR-125371 | 10APR25 | L. ONOFREL
DIMENSION: FAB NOTES REVISION: 2ND NOVEMBER 2022 | 8.   IMPEDANCE REQUIREMENTS: IF NO STACKUP IS DEFINED, THE VENDOR IS ALLOWED TO ADJUST THE DIELECTRIC | 13.  PLATING SPECIFICATION: | 9.   FILLET OPTIONS TO ENHANCE RELIABILITY AT PAD JUNCTIONS WHERE SPACING PERMITS. | 10.  THIEVING: | 11.  LAYER TO LAYER REGISTRATION SHALL BE WITHIN 0.003 INCHES. | 12.  DRILL SIZES ARE FINISHED HOLE SIZES. ALL HOLES SHALL BE LOCATED WITHIN 0.005 INCHES DTP,UNLESS SPECIFIED. | 14.  SURFACE FINISH: | 15.  SOLDERMASK: | 1.   DIMENSIONS ARE IN INCHES (EXCEPT WHERE NOTED). | ALL DOCUMENTS & SPECIFICATIONS REFERRED TO BELOW SHOULD BE THE LATEST REVISIONS. | 2.  BOARD MATERIAL:(USE CHECKED ITEMS) | 3.   ALL LAMINATES & BONDING MATERIALS SHOULD BE SELECTED FROM IPC-4101 OR IPC-4103,(TG>170 DEGC TD>300 DEGC) | 4.   REFER TO IPC-6010 SERIES, CLASS 2 FOR FABRICATION. | 5.   REFER TO LAMINATION DIAGRAM FOR OVERALL BOARD THICKNESS, TOLERANCE APPLIES AFTER ALL LAMINATION AND PLATING | 6.   BOW & TWIST NOT TO EXCEED 0.0075 INCHES (0.75%) PER LINEAR INCH AND SHOULD BE MEASURED PER IPC-TM-650, METHOD 2.4.22. | 7.   ACCEPTABILITY PER ADI SPECIFICATION TST00115. | 16.  APPLY SILKSCREEN TO BOTH SIDES USING A NON-CONDUCTIVE, EPOXY BASED INK PER ARTWORK. | ( ) FILLETS ALLOWED | (X) FILLETS NOT ALLOWED | ( ) VENDOR MAY ADD THIEVING TO COMPENSATE FOR LOW COPPER DENSITY AREAS MAINTAINING A MINIMUM | (X) VENDOR MAY NOT ADD THIEVING TO COMPENSATE FOR LOW COPPER DENSITY AREAS. | (X) LPI | ( ) OTHER_________ | COLOR | ( ) GREEN | (X) OTHER_________BLUE | (X) WHITE | ( ) OTHER | HINDER PROPER SOLDER WICKING. BARREL RELIEF ON SOLDERMASK ALLOWED IN UNFILLED VIA IN PAD HOLES. | (X) REFER TO LAMINATION DIAGRAM FOR FINISHED COPPER WEIGHT/THICKNESS REQUIRMENTS | (X) IMMERSION GOLD (ENIG) 1.58-3.94 MICRO INCHES OVER 118-236 MICRO INCHES MIN. OF ELECTROLESS NICKEL PER IPC-4552 | ( ) OSP (ORGANIC SOLDERABILITY PRESERVATIVE) | ( ) IMMERSION SILVER | ( ) SOFT WIRE BONDABLE GOLD 30-50 MICRO INCHES OF SOFT WIRE | ( ) EDGE CONNECTOR FINGERS ARE TO BE PLATED WITH 100 MICRO-INCHES(.0001") OF LOW STRESS | THICKNESS & TRACE WIDTHS TO MEET THE IMPEDANCE REQUIREMENT. IF SPECIFIED, THE VENDOR MUST | TRACE WIDTH & SPACING THAT IMPACT THE REQUIREMENTS MUST HAVE WRITTEN APPROVAL FROM ADI. | MINIMUM BARREL PLATING OF 0.001 INCHES. PLATED HOLES SHALL NOT BE ROUGH OR IRREGULAR SO AS TO | SOLDERMASK OVER BARE COPPER OR BARE GOLD (BOTH SIDES) TO MEET IPC-SM-840. | IF PRESENT,DO NOT MODIFY SOLDERMASK DEFINED PADS (MASK OPENINGS LESS THAN COPPER PAD) WITHOUT APPROVAL. | MEET THE REQUIREMENTS LISTED IN THE IMPEDANCE TABLE. ANY ADJUSTMENT MADE TO THE DEFINED STACKUP, | PROCESSES. FINISHED THICKNESS MEASURED FROM TOP COPPER TO BOTTOM COPPER. | (X)  ISOLA 370HR OR S1000-2 OR IT180 OR EQUIVALENT | ( )  ISOLA-FR408HR OR EQUIVALENT | ( )  ISOLA IS410 | ( )  MEGTRON 6 | ( )  NELCO-4000-13 | ( )  ROGERS 4350B | ( )  ROGERS 3003 | ( )  ARLON 85N | ( )  EM370D | ( )  OTHER ________________________ | UL FLAMMABILITY RATING 94V-0. BOARD MATERIAL & CONSTRUCTION SHALL MEET THE REQUIREMENTS OF UL796/UL796F. | BONDABLE GOLD OVER 100-150 MICRO INCHES OF NICKEL | NICKEL UNDER 30 MICRO-INCHES (.0003') OF GOLD | 0.100 INCH CLEARANCE FROM ALL COPPER FEATURES, | THE STARTING COPPER WEIGHT/THICKNESS CAN VARY AS LONG AS THE FINISHED COPPER | WEIGHT/THICKNESS IS NOT LESS THAN THE SPECIFIED VALUE. | UNLESS OTHERWISE SPECIFIED | HOMOGENOUS MATERIALS IN THIS BOARD SHALL BE COMPLAINT WITH THE EU DIRECTIVE 2002/95/EC | WORKMANSHIP SHALL CONFORM TO IPC-A-600, CLASS 2. | 21.  INTENTIONAL SHORTS: | 24. PANELIZATION: | 17.  FINAL ELECTRICAL TEST TO BE PERFORMED USING PROVIDED IPC-D-356A NETLIST OR ODB++ FORMAT FILE. | 25.  MINIMUM DESIGN LINE WIDTH IS .006 INCHES. | 26.  MINIMUM DESIGN LINE SPACING IS .006 INCHES. | 22.  PEMNUTS: | 23.  MANUFACTURER TO ETCH/STAMP WITH PERMANENT NON-CONDUCTIVE INK | ON SECONDARY SIDE UNLESS OTHERWISE SPECIFIED: | 18.  A TIME DOMAIN REFLECTOMETER REPORT (TDR) FOR EACH IMPEDANCE CONTROLLED LAYER & A CERTIFICATE | 19.  IF PRESENT, ALL BLIND/BURIED VIAS WITH AN ASPECT RATIO <1:1 TO BE PLATED SHUT WITH COPPER WHEN | 20.  FOR VIA FILL INFORMATION REFER TO DRILL CHART: | BOARDS TO BE SHIPPED IN ARRAY AND KEPT INTACT | PANEL TO BE SUBJECTED TO CUSTOMERS APPROVAL | PANEL SOLDER PASTE STENCIL GERBER TO BE PROVIDED TO ANALOG | IS ACCEPTABLE, ALL OTHER INSTANCES MUST BE REPORTED. | IF AN INTENTIONAL SHORT REPORT IS SUPPLIED AND DOES NOT MATCH THE FAB DATA THEN | THE PCB SHALL HAVE A VERIFICATION STAMP. | ( )  NON-CONDUCTIVE EPOXY FILL ALL 0.XXXX INCHES DRILLED VIAS | ( )  COPPER FILL ALL 0.XXXX INCHES DRILLED VIAS | ( ) PEMNUTS TO BE INSTALLED BY FABRICATOR | ( ) PEMNUTS NOT TO BE INSTALLED BY FABRICATOR | (X) NOT APPLICABLE | USED AS VIA-IN-PAD OR AS A STACKED VIA. BLIND/BURIED VIAS WITH AN ASPECT RATIO >1:1 TO BE FILLED | A. UL CODE-FLAMMABILITY RATING FOR THOSE APPROVED MATERIALS(IF APPLICABLE) | B. DATE CODE | C. LOT NUMBER | D. MANUFACTURER LOGO | CAN'T BE PERFORMED BECAUSE THE TRACE LENGTH IS TOO SHORT ON THE OUTER LAYERS AT THE PIN ESCAPES | ADI APPROVAL IS REQUIRED. | OF COMPLIANCE SHALL BE PROVIDED BY VENDOR AT TIME OF SHIPMENT. INSTANCES WHERE TDR TESTING | WITH NON-CONDUCTIVE EPOXY. | TOOLING: | FINISH: | NOTES: | MATERIAL: | TESTING: | MISCELLANEOUS: | " " | (REF) | DIA MAX | 6 LAYER STACKUP
User.12: A | C | +
User.17: 08-      -07 | L2 GND/SIGNAL
User.18: 08-      -08 | L3 GND/SIGNAL
User.19: 08-      -09 | L4 GND/SIGNAL
User.20: 08-      -10 | L5 GND/SIGNAL
User.24: SUPPLY | POWER | CONNECT EN/UVLO | TO GND FOR SHUTDOWN | OPTIONAL | OPTIONAL FOR SYNC | IN | OUT | V | LOAD | I | A | - | +
User.45: FIGURE | SIZE | 10.0 | 35.0 | 100.0 | 213.0 | 187.0 | PLATED | NON-PLATED | DRILL CHART: TOP to BOTTOM | ALL UNITS ARE IN MILS | QTY | 280 | 15 | 11 | 4 | TOLERANCE/NOTES
